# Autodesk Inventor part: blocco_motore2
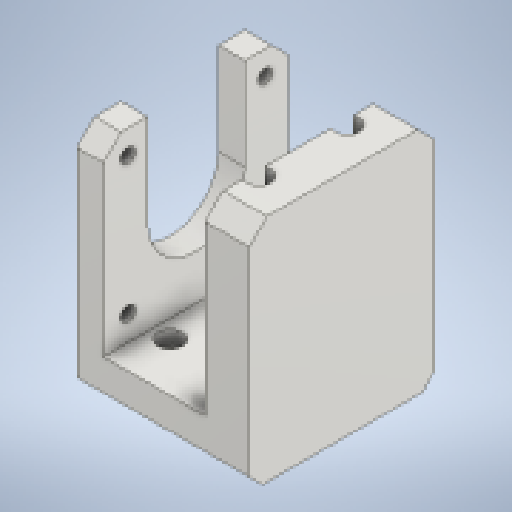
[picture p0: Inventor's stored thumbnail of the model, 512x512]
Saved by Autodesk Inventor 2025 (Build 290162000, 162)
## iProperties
Created: 2025-11
Part Number: blocco_motore2
Material: Plastica ABS
Document SubType Name: Modeling
Designer: R5800u
Density: 1.06 g/cm^3
Appearance: Acciaio
Author: R5800u
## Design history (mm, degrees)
sketch "Schizzo1"
  geometry: L1 (0, 0)-(-15, 0); L2 (-15, 0)-(-15, 52); L3 (-15, 52)-(0, 52); L4 (0, 52)-(0, 0); L5 (-15, 0)-(-47, 0); L6 (-47, 0)-(-47, 10); L7 (-47, 10)-(-15, 10); L8 (-15, 10)-(-15, 0); 1 further point
  constraints: 16 end point, 4 parallel, 2 horizontal, 2 perpendicular
  dimensions: "d0" = 15 distance of L2.end L3.end; "d1" = 52 distance of L1.end L2.end; "d2" = 32 distance of L6.end L7.end; "d3" = 10 distance of L5.end L6.end
extrude "Estrusione1" new body sketch "Schizzo1" stored distance "d4" = 42; taper "d5" = 0 deg
sketch "Schizzo2"
  geometry: L1 (0, 42)-(0, 0) reference; L2 (0, 21)-(32, 21); L3 (32, 42)-(32, 0) reference; C1 r 1.25 at (26.1, 31); C2 r 1.25 at (26.1, 11); C3 r 1.25 at (6.1, 11); C4 r 1.25 at (6.1, 31); 1 further point
  constraints: 4 centre point, 2 end point, 2 midpoint, 1 other
  dimensions: "d31" = 20 distance of C4.centre C3.centre; "d32" = 20 distance of C1.centre C2.centre; "d33" = 20 distance of C2.centre C3.centre; "d34" = 20 distance of C1.centre C4.centre; "d35" = 6.1 distance from line of L1 C3.centre
hole "Foro1" sketch "Schizzo2" at (6.1, 31), (6.1, 11), (26.1, 11), (26.1, 31) diameter "d9" = 2.9; stored, may be unused: countersink angle "d13" = 90 deg, drill point angle "d15" = 118 deg; dims "d10" = 6, "d11" = 5.5, "d12" = 2.9, "d14" = 8
sketch "Schizzo3"
  geometry: C1 r 1.45 at (6.1, 11) reference; C2 r 1.45 at (6.1, 31) reference; C3 r 1.45 at (26.1, 11) reference; C4 r 1.45 at (26.1, 31) reference; 5 further points
  constraints: 4 coincident
hole "Foro2" sketch "Schizzo3" at (6.1, 11), (6.1, 31), (26.1, 11), (26.1, 31) diameter "d16" = 2.9; stored, may be unused: countersink angle "d20" = 90 deg, drill point angle "d22" = 118 deg; dims "d17" = 6, "d18" = 5.5, "d19" = 3.5, "d21" = 8
sketch "Schizzo4"
  geometry: C1 r 1.5 at (10, 15.05) reference; C2 r 1.5 at (17, 8.05) reference; C3 r 1.5 at (17, 22.05) reference; C4 r 1.5 at (24, 15.05) reference; 1 further point
hole "Foro3" sketch "Schizzo4" at (10, 15.05), (17, 8.05), (24, 15.05), (17, 22.05) diameter "d23" = 3.4; stored, may be unused: countersink angle "d27" = 90 deg, drill point angle "d29" = 118 deg; dims "d24" = 6, "d25" = 6.5, "d26" = 3.4, "d28" = 8
sketch "Schizzo5"
  geometry: L1 (0, 0)-(-42, 0) reference; L2 (0, 10)-(0, 0) reference; L3 (-42, 10)-(0, 10) reference; L4 (-42, 0)-(-42, 10) reference; 1 further point
extrude "Estrusione2" join sketch "Schizzo5" distance "d36" = 4; taper "d37" = 0 deg
sketch "Schizzo6"
  geometry: L1 (-36, 0)-(-36, 42) reference; L2 (0, 42)-(0, 0) reference; L3 (0, 0)-(-36, 0) reference; L4 (0, 42)-(-36, 42) reference; L5 (-36, 0)-(-30, 0); L6 (-30, 0)-(-30, 42); L7 (-30, 42)-(-36, 42); L8 (-36, 42)-(-36, 0); L9 (0, 42)-(-36, 42) reference; L10 (0, 0)-(-7, 0); L11 (-7, 0)-(-7, 42); L12 (-7, 42)-(0, 42); L13 (0, 42)-(0, 0); 4 further points
  constraints: 16 end point, 4 parallel, 2 horizontal, 2 perpendicular, 2 point on line
extrude "Estrusione3" join sketch "Schizzo6" distance "d38" = 42; taper "d39" = 0 deg
sketch "Schizzo7"
  geometry: C1 r 1.45 at (24.1, -31) reference; C2 r 2.75 at (24.1, -31); C3 r 2.75 at (24.1, -11); A1 r 2.75 centre (24.1, -31) between (23, -28.48) and (23, -33.52) reference; A2 r 2.75 centre (24.1, -11) between (23, -8.48) and (23, -13.52) reference; A3 r 2.75 centre (24.1, -11) between (23, -13.52) and (23, -8.48) reference; 3 further points
  constraints: 2 centre point, 2 coincident, 1 concentric
extrude "Estrusione4" cut sketch "Schizzo7" distance "d40" = 42; taper "d41" = 0 deg
sketch "Schizzo8"
  geometry: L1 (0, 52)-(-42, 52) reference; L2 (-10, 31.15)-(-32, 31.15); L3 (-32, 31.15)-(-32, 52); L4 (-32, 52)-(-10, 52); L5 (-10, 52)-(-10, 31.15); 4 further points
  constraints: 8 end point, 2 parallel, 1 horizontal, 1 perpendicular, 1 point on line, 2 other
extrude "Estrusione5" cut sketch "Schizzo8" stored distance "d42" = 42; taper "d43" = 0 deg
sketch "Schizzo9"
  geometry: L1 (-32, 31.15)-(-32, 52) reference; L2 (-42, 52)-(-32, 52) reference; L3 (-42, 0)-(-42, 52) reference; L4 (-42, 0)-(0, 0) reference; L5 (0, 0)-(0, 52) reference; L6 (-10, 52)-(0, 52) reference; L7 (-10, 52)-(-10, 31.15) reference; A1 r 11 centre (-21, 31.15) between (-32, 31.15) and (-10, 31.15) reference; 1 further point
extrude "Estrusione6" join sketch "Schizzo9" distance "d44" = 4; taper "d45" = 0 deg
sketch "Schizzo10"
  geometry: L1 (0, 0)-(0, 52) reference; L2 (42, 0)-(0, 0) reference; L3 (42, 0)-(42, 52) reference; L4 (0, 52)-(42, 52) reference; 1 further point
extrude "Estrusione7" join sketch "Schizzo10" distance "d46" = 3; taper "d47" = 0 deg
chamfer "Smusso2" distance "d48" = 4; stored, may be unused: second distance "d49" = 2, angle "d50" = 45 deg
sketch "Schizzo11"
  geometry: C1 r 1.25 at (-5.5, 46.65) reference; C2 r 1.25 at (-36.5, 46.65) reference; C3 r 1.25 at (-36.5, 15.65) reference; C4 r 1.25 at (-5.5, 15.65) reference; 1 further point
hole "Foro4" sketch "Schizzo11" at (-5.5, 15.65), (-5.5, 46.65), (-36.5, 46.65), (-36.5, 15.65) diameter "d51" = 3.2; stored, may be unused: countersink angle "d55" = 90 deg, drill point angle "d57" = 118 deg; dims "d52" = 6, "d53" = 6, "d54" = 1.5, "d56" = 12
chamfer "Smusso3" distance "d58" = 3; stored, may be unused: second distance "d59" = 2, angle "d60" = 45 deg
sketch "Schizzo12"
  geometry: C1 r 1.35 at (-21, 4) reference; 1 further point
hole "Foro5" sketch "Schizzo12" at (-21, 4) diameter "d61" = 2.7; stored, may be unused: countersink angle "d65" = 90 deg, drill point angle "d67" = 0 deg; dims "d62" = 6, "d63" = 5.5, "d64" = 2.9, "d66" = 10
node "Solido1"
node "Riferimento5"
node "Riferimento6"
node "Riferimento7"
node "Riferimento8"
node "Linea chiusa proiettata1"
node "Riferimento10"
node "Linea chiusa proiettata2"
node "Linea chiusa proiettata3"
node "Riferimento11"
node "Riferimento12"
node "Riferimento13"
node "Riferimento14"
node "Riferimento15"
